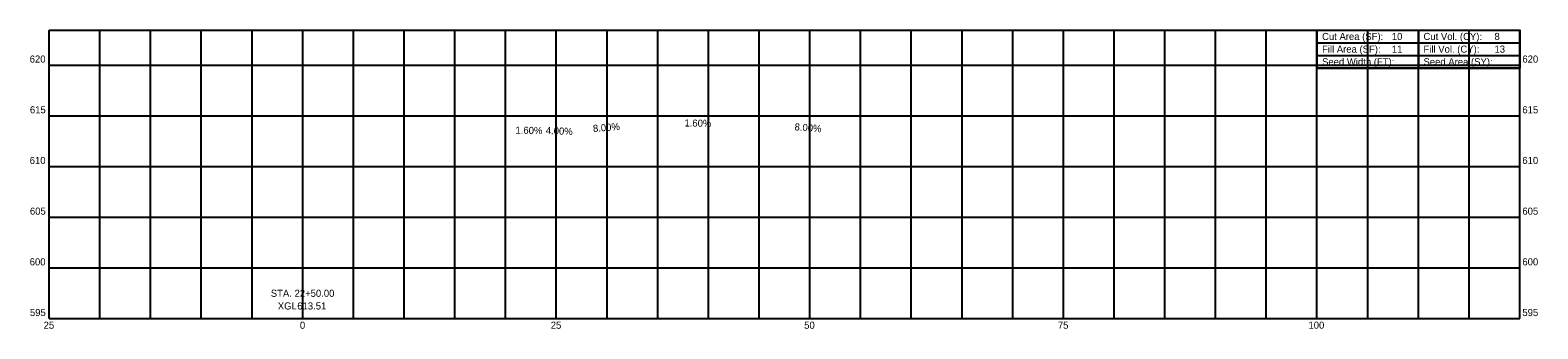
# Model space of a CAD drawing. Extents: x -27 to 122, y 594 to 623.
import ezdxf

# ---------------------------------------------------------------- set-up
doc = ezdxf.new("R2010")
doc.units = 0
for name, color, linetype in [('Default', 7, 'Continuous'), ('SH_Data', 7, 'Continuous'), ('SH_Major_Grid_Line', 7, 'Continuous'), ('SH_Masking', 7, 'Continuous'), ('SH_Text', 7, 'Continuous')]:
    doc.layers.add(name, color=color, linetype=linetype)

msp = doc.modelspace()

# ---------------------------------------------------------------- linework, layer by layer
at = {"layer": 'Default'}
msp.add_circle((120, 623.45), 0.000417, dxfattribs=at)
msp.add_circle((120, 623.45), 0.000417, dxfattribs=at)
msp.add_circle((120, 623.45), 0.000417, dxfattribs=at)
msp.add_circle((120, 623.45), 0.000417, dxfattribs=at)
msp.add_circle((120, 623.45), 0.000417, dxfattribs=at)
msp.add_circle((120, 623.45), 0.000417, dxfattribs=at)
msp.add_circle((120, 623.45), 0.000417, dxfattribs=at)
msp.add_circle((120, 623.45), 0.000417, dxfattribs=at)
msp.add_circle((120, 623.45), 0.000417, dxfattribs=at)
msp.add_circle((120, 623.45), 0.000417, dxfattribs=at)
msp.add_circle((120, 623.45), 0.000417, dxfattribs=at)
msp.add_circle((120, 623.45), 0.000417, dxfattribs=at)
at = {"layer": 'SH_Data'}
for p, q in [((100, 623.45), (120, 623.45)), ((100, 623.45), (100, 620.95)), ((110, 623.45), (110, 619.7)), ((120, 623.45), (120, 620.95)), ((100, 622.2), (120, 622.2)), ((100, 620.95), (120, 620.95)), ((108.3, 620.33), (108.3, 620.33)), ((117.95, 620.33), (117.95, 620.33))]:
    msp.add_line(p, q, dxfattribs=at)
msp.add_lwpolyline([(100, 620.95), (100, 619.7), (120, 619.7), (120, 620.95)], dxfattribs=at)
at = {"layer": 'SH_Major_Grid_Line'}
for p, q in [((-25, 623.45), (120, 623.45)), ((-25, 595), (-25, 623.45)), ((-20, 595), (-20, 623.45)), ((-15, 595), (-15, 623.45)), ((-10, 595), (-10, 623.45)), ((-5, 595), (-5, 623.45)), ((0, 595), (0, 623.45)), ((5, 595), (5, 623.45)), ((10, 595), (10, 623.45)), ((15, 595), (15, 623.45)), ((20, 595), (20, 623.45)), ((25, 595), (25, 623.45)), ((30, 595), (30, 623.45)), ((35, 595), (35, 623.45)), ((40, 595), (40, 623.45)), ((45, 595), (45, 623.45)), ((50, 595), (50, 623.45)), ((55, 595), (55, 623.45)), ((60, 595), (60, 623.45)), ((65, 595), (65, 623.45)), ((70, 595), (70, 623.45)), ((75, 595), (75, 623.45)), ((80, 595), (80, 623.45)), ((85, 595), (85, 623.45)), ((90, 595), (90, 623.45)), ((95, 595), (95, 623.45)), ((100, 595), (100, 623.45)), ((105, 595), (105, 623.45)), ((110, 595), (110, 623.45)), ((115, 595), (115, 623.45)), ((120, 595), (120, 623.45)), ((-25, 620), (120, 620)), ((-25, 615), (120, 615)), ((-25, 610), (120, 610)), ((-25, 605), (120, 605)), ((-25, 600), (120, 600)), ((-25, 595), (120, 595))]:
    msp.add_line(p, q, dxfattribs=at)
at = {"layer": 'SH_Masking'}
msp.add_lwpolyline([(100, 623.45), (120, 623.45), (120, 619.7), (100, 619.7)], close=True, dxfattribs=at)

# ---------------------------------------------------------------- texts
at = {"layer": 'SH_Text'}
for s, p in [('Cut Area (SF):', (100.5, 622.48)), ('10', (107.38, 622.48)), ('Cut Vol. (CY):', (110.5, 622.48)), ('8', (117.5, 622.48)), ('Fill Area (SF):', (100.5, 621.23)), ('11', (107.38, 621.23)), ('Fill Vol. (CY):', (110.5, 621.23)), ('13', (117.5, 621.23)), ('620', (-26.92, 620.25)), ('Seed Width (FT):', (100.5, 619.98)), ('Seed Area (SY):', (110.5, 619.98)), ('620', (120.25, 620.25)), ('615', (-26.9, 615.25)), ('615', (120.25, 615.25)), ('610', (-26.92, 610.25)), ('610', (120.25, 610.25)), ('605', (-26.9, 605.25)), ('605', (120.25, 605.25)), ('600', (-26.92, 600.25)), ('600', (120.25, 600.25)), ('STA. 22+50.00', (-3.15, 597.15)), ('XGL ', (-2.46, 595.9)), ('613.51', (-0.54, 595.9)), ('595', (-26.9, 595.25)), ('25', (-25.55, 594)), ('0', (-0.28, 594)), ('25', (24.45, 594)), ('50', (49.44, 594)), ('75', (74.45, 594)), ('100', (99.16, 594)), ('595', (120.25, 595.25))]:
    msp.add_text(s, height=0.7, dxfattribs=at).set_placement(p)
for s, rotation, p in [('1.60%', 359.0833, (20.97, 613.24)), ('8.00%', 4.5739, (28.64, 613.4)), ('1.60%', 359.0833, (37.63, 613.95)), ('8.00%', 355.4261, (48.47, 613.58)), ('4.00%', 357.7094, (23.95, 613.21))]:
    msp.add_text(s, height=0.7, rotation=rotation, dxfattribs=at).set_placement(p)

doc.saveas('drawing.dxf')
